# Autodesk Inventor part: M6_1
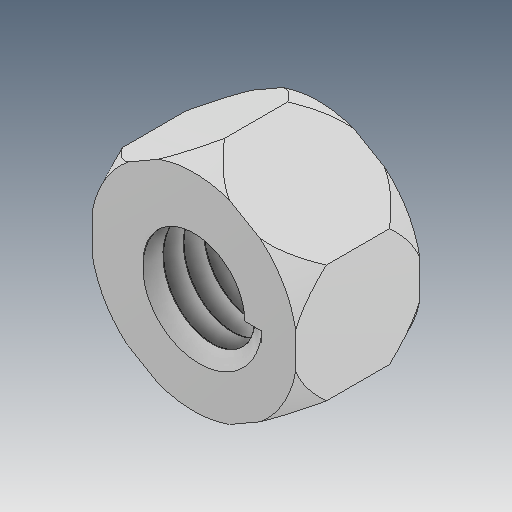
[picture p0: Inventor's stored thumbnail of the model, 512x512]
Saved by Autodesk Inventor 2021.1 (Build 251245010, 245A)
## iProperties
Created: 2021-05
Part Number: M6_1
Material: Ogólny
Document SubType Name: Modeling
Designer: user
Density: 1 g/cm^3
Appearance: Domyślna
Author: user
Revision Number: ÈÎºÎ
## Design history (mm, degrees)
feature "ÊäÈë1"
node "Bryła1"
